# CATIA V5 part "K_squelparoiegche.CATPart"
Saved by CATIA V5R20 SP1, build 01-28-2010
Part number: squelparoiegch
Property "Longueur11": 0 mm
Property "Longueur12": 0 mm
Property "Longueur13": 0 mm
Publications: "LongueurH=0", "hauteur", "Longueurbas", "rayonaxecoté", "distbas_ctregalet", "distV_ctregalet", "entraxegalets"
Bounding box of the stored display mesh (mm): x -20 to 0, y -50 to 360, z -90 to 170
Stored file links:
  G:\Khaled_CFAO_2011\SIL\SIL_GR2\zthiebault\Khaled\CAD_ThinkMOTION\K_squelparoiegche.CATPart
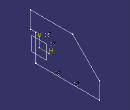
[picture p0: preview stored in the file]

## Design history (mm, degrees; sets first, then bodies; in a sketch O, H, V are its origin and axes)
Parameters
  `épaisseurplaque` = 1 mm
  `LongueurH=0` = 100 mm
  hauteur = 260 mm
  Longueurbas = 380 mm
  `rayonaxecoté` = 0.2 mm
  distbas_ctregalet = 13 mm
  distV_ctregalet = 110 mm
  entraxegalets = 110 mm
  `dist_bâticerclecontactgalet` = 10.41 mm
  Rgaletaucontact = 0.9 mm
Body1 (main body)
  DatumPoint1
  DatumCurve1 to DatumCurve5
  Point1: stored without definition
  Point2: stored without definition
  Line1: stored without definition
  Point3: stored without definition
  Sketch1 on yz-plane, origin (0, 0, 0), H (0, 1, 0), V (0, 0, 1)
    line L1 (-50, 170) -> (-50, 70)
    line L2 (-50, 70) -> (-20, 70)
    line L3 (-20, 70) -> (-20, -90)
    line L4 (-20, -90) -> (360, -90)
    line L5 (360, -90) -> (360, 10)
    line L6 (360, 10) -> (200, 170)
    line L7 (200, 170) -> (-50, 170)
    point P8 (46.5, 88)
    point P9 (110, -77)
    point P10 (220, -77)
    axis line L8 (110, -77) -> (220, -77)
    point P11 (80, 59)
    reference projected line E1 (69.7776, 50) -> (169.7776, 50) from edge of DatumCurve5
    reference projected line E2 (287.8238, -68) -> (54.4905, -68) from Line1
    distance L7 L4 = 260 {= hauteur}
    length L1 = 100 {= `LongueurH=0`}
    length L4 = 380 {= Longueurbas}
    angle L6 H = 45
    length L5 = 100
    distance P8 L1 = 96.5
    length L2 = 30
    distance P9 L4 = 13 {= distbas_ctregalet}
    distance V P9 = 110 {= distV_ctregalet}
    length L8 = 110 {= entraxegalets}
    distance P11 E1 = 9 {= 9mm}
    distance P11 V = 80
    distance E2 L4 = 22
    distance P8 L7 = 82
    distance L3 V = 20
    vertical: L1 V, L3 V, L5 V
    horizontal: L2 H, L4 H, L7 H
    parallelism: L8 L4
  Line2: type Normal, RefPoint Sketch1.P8, RefSkin yz-plane, Start 0, End 20
  Plane1: type OffsetPt, RefPlane yz-plane, RefPoint Sketch1.P8
  Plane2: type OffsetPt, RefPlane yz-plane, RefPoint Sketch1.P9
  Plane3: type OffsetPt, RefPlane yz-plane, RefPoint Sketch1.P10
  Line3: type Normal, RefPoint Sketch1.P9, RefSkin Plane2, Start 0, End 10.414 {= 10.414mm}
  Line4: type Normal, RefPoint Sketch1.P10, RefSkin Plane3, Start 0, End 10.41
  Plane4: type OffsetPt, RefPlane yz-plane, RefPoint Sketch1.P11
  Line5: type Normal, RefPoint Sketch1.P11, RefSkin Plane4, Start 0, End 10.41 {= 10.41mm}
  Plane5: type OffsetPt, RefPlane yz-plane, RefPoint Sketch1.P11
